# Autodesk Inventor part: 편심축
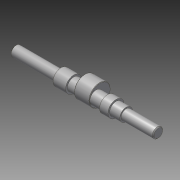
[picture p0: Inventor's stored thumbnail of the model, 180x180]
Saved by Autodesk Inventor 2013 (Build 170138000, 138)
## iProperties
Company: 한국ATC센터
Created: 2014-02
Part Number: 편심축
Document SubType Name: Modeling
Designer: KYOUNG IL JANG
Density: 7.86 g/cm^3
Mass: 251.16 g
Surface Area: 94.6899 cm^2
Volume: 31.9542 cm^3
Material: 강, 연강
Vendor: CBT Solutions
Author: KYOUNG IL JANG
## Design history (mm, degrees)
sketch "스케치1"
  geometry: L1 (-84.5, 0)-(84.5, 0); L2 (-84.5, 0)-(-84.5, 6); L3 (-84.5, 6)-(-30.5, 6); L4 (-30.5, 6)-(-30.5, 9.5); L5 (-30.5, 9.5)-(-15.5, 9.5); L6 (-15.5, 9.5)-(-15.5, 7.5); L7 (-15.5, 7.5)-(46.5, 7.5); L8 (84.5, 6)-(84.5, 0); L9 (34.5, 7.5)-(34.5, 9.5); L10 (34.5, 9.5)-(24.5, 9.5); L11 (24.5, 9.5)-(24.5, 7.5); L12 (46.5, 7.5)-(46.5, 6); L13 (46.5, 6)-(84.5, 6); 2 further points
  constraints: 26 end point, 6 parallel, 6 perpendicular, 2 point on line, 1 coincident, 1 horizontal, 1 midpoint
  dimensions: "d1" = 12 diameter of L3 L1; "d2" = 15 diameter of L7 L1; "d4" = 15 distance of L4.end L5.end; "d5" = 19 diameter of L5 L1; "d24" = 10 distance of L9.end L10.end; "d25" = 19 diameter of L10 L1; "d27" = 40 distance between parallel lines of L11 L6; "d28" = 54 distance of L2.end L3.end; "d29" = 50 distance between parallel lines of L8 L9; "d41" = 38 distance between parallel lines of L8 L12; "d42" = 12 diameter of L13 L1
revolve "회전1" stored, may be unused: angle "d6" = 90 deg
node "작업 평면1"
sketch "스케치2"
  geometry: C1 r 7.5 at (0, 0) reference; C2 r 12.5 at (0, 4.5); 1 further point
  constraints: 1 centre point, 1 vertical alignment
  dimensions: "d8" = 4.5 distance of point (0, 0) C2.centre; "d9" = 25 diameter of C2
extrude "돌출1" join sketch "스케치2" distance "d10" = 18; taper "d11" = 0 deg
chamfer "모따기1" distance "d12" = 1; stored, may be unused: second distance "d13" = 2, angle "d14" = 45 deg
chamfer "모따기2" distance "d15" = 0.5; stored, may be unused: second distance "d16" = 2, angle "d17" = 45 deg
node "작업 평면2"
sketch "스케치3"
  geometry: L1 (4, -2)-(18, -2); L2 (18, 2)-(4, 2); L3 (27, 5)-(27, -5) reference; L4 (-137, -2)-(-123, -2); L5 (-123, 2)-(-137, 2); L6 (-142, -5)-(-142, 5) reference; A1 r 2 centre (18, 0) between (18, -2) and (18, 2); A2 r 2 centre (4, 0) between (4, 2) and (4, -2); A3 r 2 centre (-123, 0) between (-123, -2) and (-123, 2); A4 r 2 centre (-137, 0) between (-137, 2) and (-137, -2); 2 further points
  constraints: 8 end point, 8 point on circle, 8 tangent, 4 centre point, 2 horizontal, 2 horizontal alignment, 2 parallel, 1 midpoint
  dimensions: "d18" = 7 distance edge to line of A1 L3; "d19" = 4 distance between parallel lines of L2 L1; "d20" = 18 dimension on A1 A2; "d43" = 4 distance between parallel lines of L5 L4; "d44" = 18 dimension on A3 A4; "d45" = 3 distance edge to line of A4 L6
extrude "돌출2" cut sketch "스케치3" distance "d21" = 2.5; taper "d22" = 0 deg
revolve "회전2" stored, may be unused: angle "d26" = 90 deg
node "솔리드1"
other parameters: "d7" = 8.5
